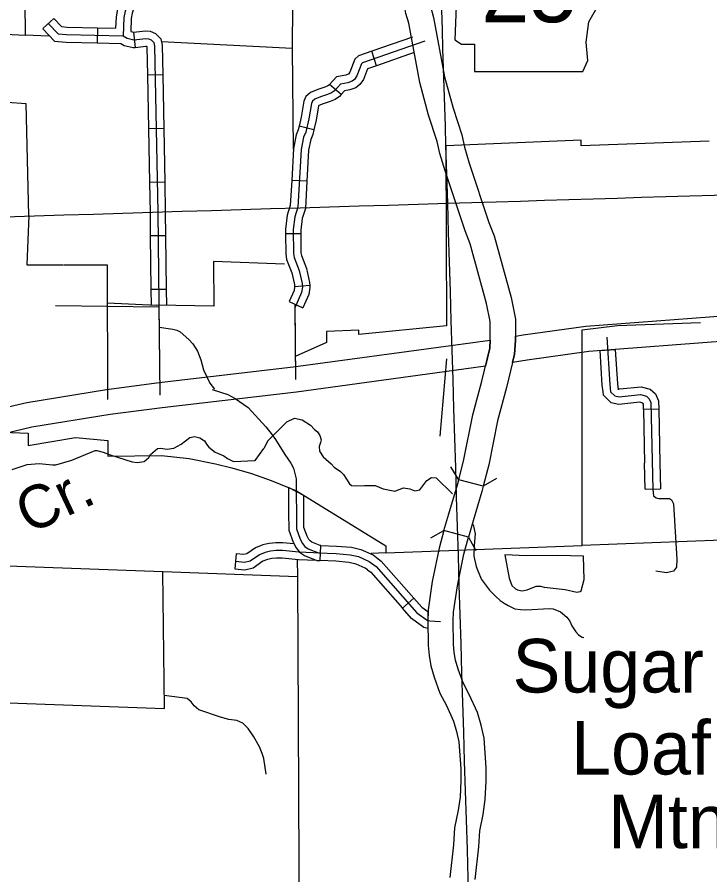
# Model space of a CAD drawing. Extents: x 1212896 to 1368412, y 378476 to 478763.
# Drawn here: x 1307448 to 1314266, y 418869 to 427313 of the extents above; entities that cross this region are included whole.
import ezdxf

# ---------------------------------------------------------------- set-up
doc = ezdxf.new("R2010")
doc.units = 0
for name, color, linetype in [('Level 10', 7, 'Continuous'), ('Level 21', 7, 'Continuous'), ('Level 31', 7, 'Continuous'), ('Level 32', 7, 'Continuous'), ('Level 33', 7, 'Continuous'), ('Level 34', 7, 'Continuous'), ('Level 35', 7, 'Continuous'), ('Level 37', 7, 'Continuous'), ('Level 4', 7, 'Continuous'), ('Level 45', 7, 'Continuous'), ('Level 5', 7, 'Continuous'), ('Level 50', 7, 'Continuous'), ('Level 6', 7, 'Continuous'), ('Level 60', 7, 'Continuous')]:
    doc.layers.add(name, color=color, linetype=linetype)

msp = doc.modelspace()

# ---------------------------------------------------------------- linework, layer by layer
at = {"layer": 'Level 10'}
for p, q in [((1312036, 422695.7), (1311793.8, 422757.6)), ((1311889.8, 422192), (1311649.1, 422259.6))]:
    msp.add_line(p, q, dxfattribs=at)
for points in [[(1312101.2, 424053.2), (1312103.2, 424136.8), (1312103.1, 424315.1), (1312067.8, 424494.4), (1311905.9, 425081.2), (1311856.5, 425207.6), (1311659.3, 425799.4), (1311608, 425970.9), (1311582.1, 426088.6), (1311498.2, 426346.7), (1311411.6, 426668.1), (1311301.9, 427252), (1311275.1, 427350.2), (1311256.4, 427448.6), (1311213.3, 427592.5), (1311094.4, 428094.4), (1310996, 428549), (1310987.9, 428618.5), (1310955.4, 428743.4), (1310838.3, 429123.9), (1310615.3, 430034.4), (1310613.6, 430042)], [(1310861.3, 430078.1), (1311079.3, 429190.5), (1311195.9, 428811.7), (1311234.2, 428664.7), (1311242.9, 428590.1), (1311338.2, 428149.7), (1311454.9, 427657.2), (1311499.6, 427507.9), (1311518.9, 427406.5), (1311545.7, 427308), (1311655.5, 426723.8), (1311738, 426418), (1311823.6, 426154.3), (1311850.2, 426033.7), (1311897.7, 425874.8), (1312091.7, 425292.7), (1312143.5, 425160.2), (1312311.2, 424551.9), (1312353.1, 424339.6), (1312353.2, 424130.6), (1312344.2, 423994.3)], [(1312353.2, 424171.8), (1312429.5, 424184.3), (1313046.9, 424270.4), (1314436.2, 424375.9), (1315435.1, 424457.1), (1315765.3, 424476.7), (1315994, 424498.2), (1317007.5, 424546.2), (1317125.5, 424522), (1317237.2, 424474), (1317334.6, 424414.2), (1317419.1, 424356.6), (1317529.3, 424271.9), (1318836.6, 423178.5), (1318957.9, 423054.3), (1319038.1, 422968.1), (1319211.4, 422756.1), (1319317.3, 422607.5)], [(1319317.3, 422176.8), (1319012.6, 422604.2), (1318849.6, 422803.7), (1318777, 422881.8), (1318666.6, 422994.8), (1317372.9, 424076.8), (1317272.5, 424154), (1317198.7, 424204.2), (1317121.7, 424251.5), (1317050.2, 424282.2), (1316988, 424295), (1316011.6, 424248.8), (1315784.4, 424227.4), (1315452.7, 424207.7), (1314455.8, 424126.6), (1313073.7, 424021.7), (1312467, 423937.1), (1312324.6, 423913.8)], [(1311716.1, 424081.9), (1312103.2, 424133.9)], [(1312103.2, 424133.9), (1312101.2, 424053.2), (1312058.1, 423875.6)], [(1312324.6, 423913.8), (1312344.2, 423994.3), (1312353.2, 424130.6), (1312353.2, 424171.8)], [(1301320.2, 422292.8), (1304147.7, 422160.1), (1304233, 422184.8), (1304524.9, 422302.6), (1305075, 422560.6), (1305253.1, 422635.8), (1305725.3, 422854.2), (1305957.8, 422953.9), (1306173.5, 423053), (1306858.2, 423329.3), (1307040.3, 423390.4), (1307270.6, 423456.6), (1307542.5, 423520.2), (1308327.5, 423647.9), (1308845.2, 423714.9), (1310164.8, 423870.3), (1311716.1, 424081.9)], [(1311793.8, 422757.6), (1311845.5, 422959.7), (1311932.9, 423396.3), (1312022.9, 423730.3), (1312101.2, 424053.2)], [(1312344.2, 423994.3), (1312265.2, 423668.3), (1312176.4, 423339.1), (1312089.3, 422904.1), (1312036, 422695.7)], [(1312058.1, 423875.6), (1311749.9, 423834.2)], [(1311749.9, 423834.2), (1310196.4, 423622.3), (1308875.9, 423466.8), (1308363.6, 423400.5), (1307591.2, 423274.9), (1307333.7, 423214.6), (1307114.5, 423151.6), (1306944.8, 423094.7), (1306272.5, 422823.4), (1306059.3, 422725.4), (1305827.1, 422625.8), (1305354.2, 422407.1), (1305176.7, 422332.2), (1304624.9, 422073.4), (1304314.8, 421948.2), (1304177.4, 421908.4), (1301308.8, 422043.1)], [(1311649.1, 422259.6), (1311695.3, 422424.1), (1311781.7, 422710.2), (1311793.8, 422757.6)], [(1312036, 422695.7), (1312022.6, 422643.1), (1311935.4, 422354.2), (1311889.8, 422192)], [(1311649.1, 422259.6), (1311600.3, 422085.7), (1311534.2, 421755.5), (1311493.7, 421477.9), (1311489.2, 421373.5), (1311493.8, 421126.9), (1311502.5, 421027.4), (1311518.4, 420925.4), (1311551.9, 420815.9), (1311609, 420658.6), (1311672.4, 420535.6), (1311742.9, 420381), (1311772.4, 420280.5), (1311795.6, 420177.4), (1311815.4, 419912.8), (1311815.6, 419799.5), (1311806.9, 419635.4), (1311787.7, 419505.7), (1311753.4, 419332.3), (1311744.3, 419165.4), (1311706.1, 418843.1)], [(1311955.5, 418823.3), (1311993.5, 419143.9), (1312002, 419301.1), (1312034.1, 419463), (1312055.9, 419610.4), (1312065.6, 419793.1), (1312065.4, 419922.3), (1312043.5, 420214.4), (1312014.5, 420343.2), (1311977.8, 420468.4), (1311897.4, 420644.8), (1311838.6, 420759), (1311789, 420895.2), (1311762.6, 420981.4), (1311750.8, 421057.5), (1311743.6, 421140.1), (1311739.3, 421370.5), (1311742.9, 421454.5), (1311780.7, 421712.8), (1311843.6, 422027.3), (1311889.8, 422192)]]:
    msp.add_lwpolyline(points, dxfattribs=at)
at = {"layer": 'Level 21'}
for p, q in [((1311788.3, 427860.3), (1311754.5, 427090.5)), ((1313074.1, 427268.2), (1313167.1, 427428.9)), ((1313048.7, 427065.1), (1313074.1, 427268.2)), ((1311754.5, 427090.5), (1311822.2, 427048.2)), ((1311822.2, 427048.2), (1311949.1, 427048.2)), ((1311949.1, 427048.2), (1311949.1, 426777.5)), ((1313065.6, 426887.5), (1313048.7, 427065.1)), ((1313014.9, 426777.5), (1313065.6, 426887.5)), ((1311949.1, 426777.5), (1313014.9, 426777.5))]:
    msp.add_line(p, q, dxfattribs=at)
at = {"layer": 'Level 31'}
for p, q in [((1313185.3, 424030.2), (1313334.9, 424041.6)), ((1313762.8, 423452.9), (1313612.9, 423449.7)), ((1310269.2, 422604.9), (1310118.8, 422681.8)), ((1313629.7, 422664.8), (1313779.7, 422668.1)), ((1310430.7, 421962.3), (1310436.9, 422112.2)), ((1310895.9, 421872.4), (1310895.9, 421872.4)), ((1311240, 421493.6), (1311352.6, 421592.7)), ((1311491.2, 421461.2), (1311490.7, 421294.8)), ((1311489.7, 421295.4), (1311490.7, 421294.8))]:
    msp.add_line(p, q, dxfattribs=at)
for points in [[(1313250.5, 424160.9), (1313280.9, 423695.9), (1313289.7, 423624.2), (1313330.5, 423583.6), (1313373.9, 423575.3), (1313582.8, 423597), (1313641.5, 423580.3), (1313668.7, 423557), (1313685, 423518.9), (1313703.4, 422662), (1313711.9, 422600.8), (1313738.2, 422580.3), (1313764.3, 422575.5), (1313869.7, 422574), (1313889.8, 422561.6), (1313908.8, 422521.7), (1313940.3, 421973), (1313938.5, 421896.7), (1313909, 421860.4), (1313840.8, 421842.5), (1313735.2, 421858.2)], [(1313334.9, 424041.6), (1313357, 423703), (1313364.3, 423643.7)], [(1313215.4, 423625.4), (1313207.6, 423689), (1313185.3, 424030.2)], [(1309366, 423647.8), (1309521.8, 423598.9), (1309595, 423558.7), (1309720.6, 423469.8), (1309895.1, 423279.3), (1309947.7, 423213.8), (1309992.1, 423155.1), (1310082.4, 423006.8), (1310140.2, 422922.6), (1310168.2, 422871.6), (1310194.6, 422767.2), (1310197.6, 422276.6), (1310233.6, 422173.7), (1310256.5, 422131), (1310280.2, 422102.1), (1310313.4, 422079.4), (1310414.5, 422039.4), (1310588.1, 422032.3), (1310725.8, 422020.7), (1310807.9, 422001.6), (1310913.7, 421954.7), (1310980.4, 421904.2), (1311380.3, 421449.7), (1311484.6, 421375.6), (1311509.6, 421368.8), (1311614.3, 421364.2)], [(1313612.9, 423449.7), (1313611.7, 423503.1), (1313607.8, 423512.3), (1313605.9, 423513.9), (1313576.3, 423522.3), (1313370.7, 423501), (1313294.6, 423515.5), (1313219.8, 423589.9), (1313215.4, 423625.4)], [(1313362.3, 423659.7), (1313367.8, 423654.2), (1313377.1, 423652.5), (1313589.5, 423674.5), (1313678.4, 423649.3), (1313732, 423603.5), (1313761.1, 423535.3), (1313762.8, 423452.9)], [(1313612.9, 423449.7), (1313624.2, 422921.8)], [(1313762.8, 423452.9), (1313774.1, 422925)], [(1313629.7, 422664.8), (1313624.2, 422921.8)], [(1313774.1, 422925), (1313779.7, 422668.1)], [(1310118.8, 422681.8), (1310120.2, 422441)], [(1310270.2, 422441.9), (1310269.2, 422604.9)], [(1310120.2, 422441), (1310121.3, 422263.4), (1310163.4, 422142.9), (1310192.7, 422088.3), (1310228.1, 422045.2), (1310277.3, 422011.5), (1310398.4, 421963.6), (1310430.7, 421962.3)], [(1310436.9, 422112.2), (1310430, 422112.5), (1310348.1, 422144.8), (1310330.4, 422156.9), (1310317.9, 422172.1), (1310301.2, 422203.4), (1310271.2, 422289.3), (1310270.2, 422441.9)], [(1310436.9, 422112.2), (1310592.7, 422105.8), (1310737.3, 422093.7), (1310831.4, 422071.7), (1310951.3, 422018.6), (1310986.3, 421992.1)], [(1310895.9, 421872.4), (1310874.7, 421888.4), (1310783.5, 421928.8), (1310713.8, 421945.1), (1310583.4, 421956), (1310430.7, 421962.3)], [(1310986.3, 421992.1), (1311030.8, 421958.4), (1311352.6, 421592.7)], [(1310895.9, 421872.4), (1310928.2, 421848), (1311240, 421493.6)], [(1311352.6, 421592.7), (1311429.9, 421504.8), (1311491.2, 421461.2)], [(1311490.7, 421294.8), (1311451.5, 421305.4), (1311328.8, 421392.6), (1311240, 421493.6)], [(1311493.1, 421460.6), (1311489.2, 421373.5), (1311489.7, 421295.4)]]:
    msp.add_lwpolyline(points, dxfattribs=at)
at = {"layer": 'Level 32'}
for p, q in [((1307809.4, 427300.1), (1307699.5, 427202.5)), ((1308240.1, 427208.9), (1308236.8, 427058.9)), ((1308592.7, 427164.5), (1308608.1, 427015.2)), ((1310986.5, 426834.9), (1310937.4, 426976.6)), ((1308880.2, 426744.6), (1308730.2, 426741.7)), ((1310636.8, 426550.2), (1310523.9, 426648.9)), ((1310369.3, 426205), (1310223, 426238)), ((1308890.3, 426216.7), (1308740.3, 426213.8)), ((1308900.3, 425688.8), (1308750.3, 425685.9)), ((1310299.7, 425697.4), (1310150, 425705.6)), ((1308908.7, 425160.3), (1308758.7, 425158.6)), ((1310239.5, 425180.6), (1310089.5, 425179.1)), ((1308914.9, 424632.4), (1308765, 424630.6)), ((1310327.7, 424670.7), (1310178.1, 424658.7)), ((1310123.8, 424512.6), (1310260.7, 424451.4))]:
    msp.add_line(p, q, dxfattribs=at)
for points in [[(1310077.9, 430798.1), (1310125, 430406), (1310127.4, 430301.1), (1310122.3, 430199.4), (1308980.4, 428284.6), (1308766.4, 427904.7), (1308629.4, 427689.4), (1308576.9, 427567.3), (1308509.9, 427370.4), (1308497.2, 427308), (1308490.2, 427129.7)], [(1308491.5, 427553.3), (1308436, 427390.4), (1308421.1, 427317.2), (1308416.7, 427204.9)], [(1308633.5, 427505), (1308581.1, 427351.1), (1308570.5, 427299.2), (1308565.5, 427172.5), (1308599.4, 427165.1)], [(1307754.4, 427251.1), (1307850.5, 427149.9), (1307934.4, 427142), (1308490.2, 427129.7)], [(1307809.4, 427300.1), (1307884.9, 427220.6), (1307938.7, 427215.6), (1308240.1, 427208.9)], [(1307699, 427198.5), (1307814.8, 427076.6), (1307930, 427065.7), (1308236.8, 427058.9)], [(1308240.1, 427208.9), (1308416.7, 427204.9)], [(1308592.7, 427164.5), (1308712, 427176.8), (1308757.8, 427173.4), (1308810.7, 427150.7), (1308861.9, 427097.8), (1308874.6, 427036), (1308880.2, 426744.6)], [(1308490.2, 427129.7), (1308531.2, 427104.7), (1308595.2, 427090.7), (1308713.1, 427102.9), (1308740.1, 427100.9), (1308768.1, 427088.9), (1308794.1, 427062), (1308801.2, 427027.8), (1308832.3, 425392.2)], [(1311461.2, 427077.6), (1310846.5, 426864.2), (1310835.7, 426854.7), (1310791, 426734.2), (1310766.8, 426700.5), (1310745.7, 426682.9), (1310702.2, 426667.6), (1310630.3, 426654.5), (1310571.4, 426587.2), (1310541.7, 426567.9), (1310502, 426550.4), (1310433.4, 426529.6), (1310376.4, 426504.7), (1310354.1, 426484.7), (1310344.3, 426462.5), (1310317.9, 426311.9), (1310288.1, 426179.6), (1310266.9, 426131), (1310243.2, 426011.5), (1310212.1, 425443.1), (1310180.2, 425346.5), (1310165.5, 425221.1), (1310167.9, 424987.7), (1310174.6, 424945.8), (1310224.5, 424817.9), (1310252.2, 424690.8), (1310255.1, 424654.9), (1310247.3, 424601.8), (1310179.7, 424450.6), (1310186.2, 423747)], [(1311338.9, 427116), (1310937.4, 426976.6)], [(1308236.8, 427058.9), (1308468, 427053.8)], [(1308468, 427053.8), (1308502.4, 427032.8), (1308590.9, 427013.5), (1308608.1, 427015.2)], [(1308608.1, 427015.2), (1308714.3, 427026.2), (1308721.8, 427025.7), (1308723.8, 427024.8), (1308724.9, 427019.3), (1308730.2, 426741.7)], [(1310937.4, 426976.6), (1310807.2, 426931.4), (1310770.7, 426899.2), (1310723, 426770.4), (1310710.4, 426752.9), (1310707.3, 426750.3), (1310682.6, 426741.7), (1310590.3, 426724.8), (1310523.9, 426648.9)], [(1311356.1, 426963.2), (1310986.5, 426834.9)], [(1310986.5, 426834.9), (1310895.1, 426803.2), (1310856.6, 426699.2), (1310821.1, 426650.1), (1310782.8, 426617.9), (1310721.1, 426596.2), (1310668.8, 426586.7), (1310636.8, 426550.2)], [(1308730.2, 426741.7), (1308740.3, 426213.8)], [(1308880.2, 426744.6), (1308890.3, 426216.7)], [(1310523.9, 426648.9), (1310520.9, 426645.5), (1310505.3, 426635.3), (1310475.5, 426622.2), (1310406.9, 426601.4), (1310334.6, 426569.7), (1310290.8, 426530.6), (1310270.7, 426484.8), (1310243, 426326.9), (1310223, 426238)], [(1310636.8, 426550.2), (1310620.2, 426531.1), (1310576.9, 426502.9), (1310527.6, 426481.2), (1310458.9, 426460.4), (1310416.7, 426442), (1310415.2, 426440.6), (1310390.1, 426297.5), (1310369.3, 426205)], [(1310223, 426238), (1310215.2, 426203.5), (1310193.6, 426154), (1310167.2, 426021.1), (1310150, 425705.6)], [(1308740.3, 426213.8), (1308750.3, 425685.9)], [(1308890.3, 426216.7), (1308900.3, 425688.8)], [(1310369.3, 426205), (1310358.4, 426156.5), (1310337.6, 426108.9), (1310316.4, 426002.3), (1310299.7, 425697.4)], [(1308750.3, 425685.9), (1308756, 425391), (1308758.7, 425158.6)], [(1308900.3, 425688.8), (1308905.9, 425393.4), (1308908.7, 425160.3)], [(1310150, 425705.6), (1310136.4, 425457.4), (1310105.2, 425363.1), (1310089.1, 425225.2), (1310089.5, 425179.1)], [(1310299.7, 425697.4), (1310285.1, 425429.3), (1310252.4, 425330.5), (1310239.2, 425217.2), (1310239.5, 425180.6)], [(1308832.3, 425392.2), (1308853.7, 423589.9)], [(1308758.7, 425158.6), (1308765, 424630.6)], [(1308908.7, 425160.3), (1308914.9, 424632.4)], [(1310089.5, 425179.1), (1310091.6, 424981.2), (1310100.5, 424925.7), (1310151.1, 424795.8), (1310176.5, 424679.5), (1310178.1, 424658.7)], [(1310239.5, 425180.6), (1310241.4, 424993.9), (1310246.1, 424965.3), (1310295.2, 424839.3), (1310325.2, 424701.6), (1310327.7, 424670.7)], [(1308765, 424630.6), (1308766.7, 424480.6)], [(1308914.9, 424632.4), (1308916.8, 424476.4)], [(1310178.1, 424658.7), (1310178.2, 424657.4), (1310173.3, 424623.3), (1310123.8, 424512.6)], [(1310327.7, 424670.7), (1310329.1, 424652.5), (1310318.7, 424581), (1310260.7, 424451.4)], [(1308335.3, 424467.4), (1308843.4, 424459.5)], [(1311675.4, 423948.9), (1311608.7, 423187.5)]]:
    msp.add_lwpolyline(points, dxfattribs=at)
at = {"layer": 'Level 33'}
msp.add_lwpolyline([(1309366, 423647.8), (1309521.8, 423598.9), (1309595, 423558.7), (1309720.6, 423469.8), (1309895.1, 423279.3), (1309947.7, 423213.8), (1309992.1, 423155.1), (1310082.4, 423006.8), (1310140.2, 422922.6), (1310168.2, 422871.6), (1310194.6, 422767.2), (1310195.3, 422650.2)], dxfattribs=at)
at = {"layer": 'Level 34'}
for points in [[(1307907.8, 424874.5), (1308334.7, 424874.8), (1308336.6, 423548)], [(1307825.1, 424475.5), (1308335.3, 424467.4)], [(1308335.3, 424467.4), (1308843.4, 424459.5)], [(1308843.2, 424477.8), (1308853.7, 423589.9)], [(1310179.4, 424487.8), (1310186.2, 423747)], [(1308845.7, 424261.5), (1308981.6, 424240.4), (1309019.6, 424229.8), (1309053.7, 424215.2), (1309137, 424139.6), (1309175.6, 424095.2), (1309223.2, 424024.6), (1309255, 423940.8), (1309281.9, 423840.9), (1309344.1, 423709.3), (1309390.4, 423650.7)], [(1311675.4, 423948.9), (1311608.7, 423187.5)]]:
    msp.add_lwpolyline(points, dxfattribs=at)
at = {"layer": 'Level 35'}
for points in [[(1310101.8, 423329.5), (1310177.5, 423365.9), (1310254.8, 423350.1), (1310334.8, 423296.1), (1310373.2, 423253.4), (1310403.3, 423229.7), (1310428.6, 423194.9), (1310439, 423150.9), (1310435.3, 423124.8), (1310421.8, 423085.6), (1310425.2, 423039.5), (1310458.7, 422984.8), (1310538.2, 422914.5), (1310567.5, 422882.7), (1310629.7, 422840.3), (1310661, 422811.6), (1310717.8, 422718), (1310739.9, 422701.2), (1310783.8, 422697.7), (1310865.5, 422703.6), (1310972.3, 422701.7), (1311049.4, 422669.5), (1311165.4, 422646.7), (1311251.8, 422677.7), (1311313.8, 422668.3), (1311362.3, 422650.4), (1311412.6, 422660.4), (1311480.4, 422750.4), (1311526, 422779.7), (1311573, 422777.3), (1311732.1, 422619.9)], [(1310101.8, 423329.5), (1309913.8, 423143.4), (1309874.8, 423065.2)], [(1307398.3, 422858.2), (1307546.4, 422909.9), (1307666, 422920.2), (1307795.9, 422904.1), (1307829.7, 422906.9), (1307987, 422951.7), (1308216.3, 423046.4), (1308232.3, 423046.5), (1308293.3, 423030.2), (1308363.4, 423002.9), (1308579.5, 422934), (1308630.4, 422928.6), (1308697, 422938.1), (1308743.7, 422976.9), (1308759.3, 423007.1), (1308828.5, 423065), (1308857.4, 423069.3), (1308923.3, 423061), (1308989.1, 423069.7), (1309061.5, 423108.6), (1309147.6, 423174.6), (1309194.4, 423184.1), (1309247.3, 423172.3), (1309291.6, 423142.1), (1309310.8, 423110.2)], [(1309310.8, 423110.2), (1309335.1, 423079.4), (1309396.4, 423031), (1309480.6, 422994.8), (1309517.5, 422968.5), (1309576.9, 422938.8), (1309792, 422949.1), (1309874.8, 423065.2)], [(1311936.2, 422318.7), (1311957.1, 422226.3), (1311945.6, 422111.7), (1311943.3, 422005.1), (1311966.5, 421903.8), (1311981.3, 421861.3), (1312018.8, 421775.6), (1312096, 421673.4), (1312160.7, 421607.9), (1312203.2, 421570.5), (1312242.3, 421545.1), (1312282.3, 421519.6), (1312347.4, 421487.5), (1312400.9, 421480.4), (1312455.9, 421479.6), (1312688.3, 421490.2), (1312725.4, 421486.7), (1312796.7, 421459.2), (1312858.6, 421407), (1312886.3, 421366), (1312907.2, 421319.7), (1312947.6, 421261.2), (1312974.8, 421232.2), (1313009.7, 421210.6), (1313024.9, 421206.4)], [(1312247.5, 422018.6), (1312289.1, 421788.7), (1312317.1, 421716.6), (1312352.3, 421686), (1312373.7, 421675.8), (1312416, 421666.6), (1312435.8, 421668.9), (1312468.7, 421674.7), (1312555.1, 421712.4), (1312599.1, 421712.2), (1312636.6, 421699.7), (1312841.4, 421677), (1312956.3, 421651.7), (1312991.1, 421657.1), (1313000.7, 421666.5), (1313028.7, 421776.9), (1313021.5, 422006.4), (1312765.4, 422012.9), (1312462.8, 422008.4), (1312247.5, 422018.6)]]:
    msp.add_lwpolyline(points, dxfattribs=at)
at = {"layer": 'Level 37'}
for points in [[(1311793.8, 422757.6), (1311717.3, 422886.6)], [(1312165.1, 422772.2), (1312036, 422695.7)], [(1311518.4, 422186.1), (1311649.1, 422259.6)], [(1311889.8, 422192), (1311963.3, 422061.3)]]:
    msp.add_lwpolyline(points, dxfattribs=at)
at = {"layer": 'Level 4'}
for points in [[(1310107.3, 430000.7), (1310158.5, 427433), (1310156.1, 427003.7), (1310165.3, 426013.1)], [(1310203, 421973.1), (1310206.5, 421803.7), (1310223.6, 418254.8)]]:
    msp.add_lwpolyline(points, dxfattribs=at)
at = {"layer": 'Level 45'}
msp.add_line((1309604, 422028.8), (1309590.6, 421880.6), dxfattribs=at)
for points in [[(1309895.2, 422123.7), (1309865.7, 422116.8), (1309795, 422088.4), (1309709.5, 422028.2), (1309680.1, 422021.6), (1309603.3, 422028.5)], [(1310171.9, 422127.2), (1310063.2, 422138.4), (1309992.4, 422138.3), (1309929.8, 422131.8), (1309895.2, 422123.7)], [(1310438.5, 422036.7), (1310220.9, 422045.3), (1310059.3, 422062), (1309996.3, 422062), (1309942.5, 422056.4), (1309888.8, 422043.8), (1309831.7, 422020.8), (1309741.1, 421957), (1309685.2, 421944.5), (1309596.5, 421952.4)], [(1309929.4, 421977.7), (1309911.1, 421973.4), (1309867.1, 421955.7), (1309771.5, 421888.4), (1309690, 421870.2), (1309589.9, 421879.1)], [(1310395.7, 421964.7), (1310215.7, 421971.9), (1310055.5, 421988.4), (1310000.2, 421988.3), (1309954.8, 421983.6), (1309929.4, 421977.7)], [(1309898.2, 419859.5), (1309874.8, 420013.8), (1309860.2, 420064.5), (1309833.6, 420129.3), (1309778.7, 420227.9), (1309722, 420310.5), (1309669, 420362.8), (1309609.5, 420387.4), (1309531.6, 420398.6), (1309448.2, 420422.9), (1309235.4, 420494.6), (1309190.2, 420532.8), (1309161.8, 420573), (1309120.6, 420604.9), (1308895.5, 420633.5)]]:
    msp.add_lwpolyline(points, dxfattribs=at)
at = {"layer": 'Level 5'}
msp.add_line((1310206.5, 421803.7), (1308880.3, 421852.2), dxfattribs=at)
for points in [[(1307755.1, 427124.3), (1307530, 427135.6)], [(1310156.1, 427003.7), (1308867.1, 427068.5)], [(1314386.1, 422162.8), (1313009.3, 422110.9)], [(1311075.7, 422038), (1310932.5, 422032.6)]]:
    msp.add_lwpolyline(points, dxfattribs=at)
at = {"layer": 'Level 6'}
for points in [[(1307530, 427135.6), (1307511.8, 429104), (1310091.2, 430806.9)], [(1307561.5, 425361.5), (1307537.6, 426460.1), (1306225.1, 426550.2), (1306226, 427201.1)], [(1306226, 427201.1), (1307530, 427135.6)], [(1314258.1, 426092.5), (1313000.2, 426045.1), (1313000, 426103.4), (1311666.4, 426046.1), (1311674.5, 424275.5)], [(1307561.5, 425361.5), (1307543.8, 424874.3), (1307899.9, 424874.5)], [(1310080.2, 424881.4), (1309380.4, 424907), (1309384.5, 424467.4), (1308822.9, 424478.1)], [(1308335.3, 424499.2), (1308822.9, 424478.1)], [(1311075.3, 422108.3), (1311075.7, 422038), (1311695.7, 422061.4), (1313009.3, 422110.9), (1313007.9, 424235.3), (1313356.9, 424276), (1314173.4, 424306.8)], [(1311674.5, 424275.5), (1310811.4, 424190), (1310811.2, 424230.1), (1310493.4, 424218.2), (1310493.9, 424109.7), (1310184.2, 423972.1)], [(1306268.2, 422610.7), (1306964, 422585.2), (1306961.1, 422900.6), (1307133.6, 423002.9), (1307142, 423232.6), (1307556.4, 423217.4), (1307557.5, 423097.3), (1308020.7, 423174), (1308339.7, 423144.2), (1308341.1, 422990.9)], [(1308341.1, 422990.9), (1308869.9, 422997.6), (1309141.3, 422968.8), (1309399.8, 422916.1), (1309561.3, 422877.5), (1309755.6, 422820.2), (1309946.8, 422752.8), (1310196.4, 422649.8), (1311075.3, 422108.3)], [(1308880.3, 421852.2), (1306273.1, 421947.5)], [(1298282, 416932.8), (1298296.1, 418277.7), (1300953.3, 418184), (1300954.1, 417707.1), (1301264.5, 417691.4), (1301267.6, 418169.4), (1302325.3, 418129.7), (1302316.8, 419451.2), (1306281.1, 419306.5), (1306275.8, 420601.1), (1308897.1, 420508), (1308880.3, 421852.2)]]:
    msp.add_lwpolyline(points, dxfattribs=at)
at = {"layer": 'Level 60'}
for points in [[(1312809.8, 388461.7), (1311685.6, 425480.9), (1311315.8, 437639.7)], [(1257400.5, 423880.1), (1274492.7, 424373.3), (1311685.6, 425480.9), (1319317.4, 425714)]]:
    msp.add_spline(points, degree=3, dxfattribs=at)

# ---------------------------------------------------------------- texts
at = {"layer": 'Level 21'}
msp.add_text('25', height=633.6, dxfattribs=at).set_placement((1312017.4, 427262.7))
at = {"layer": 'Level 35'}
msp.add_text('Cr.', height=422.4, rotation=25.27342, dxfattribs=at).set_placement((1307563.5, 422217.5))
at = {"layer": 'Level 50'}
for s, p in [('Sugar', (1312324, 420664.2)), ('Loaf', (1312901.2, 419857)), ('Mtn.', (1313265.8, 419131.7))]:
    msp.add_text(s, height=528, dxfattribs=at).set_placement(p)

doc.saveas('drawing.dxf')
